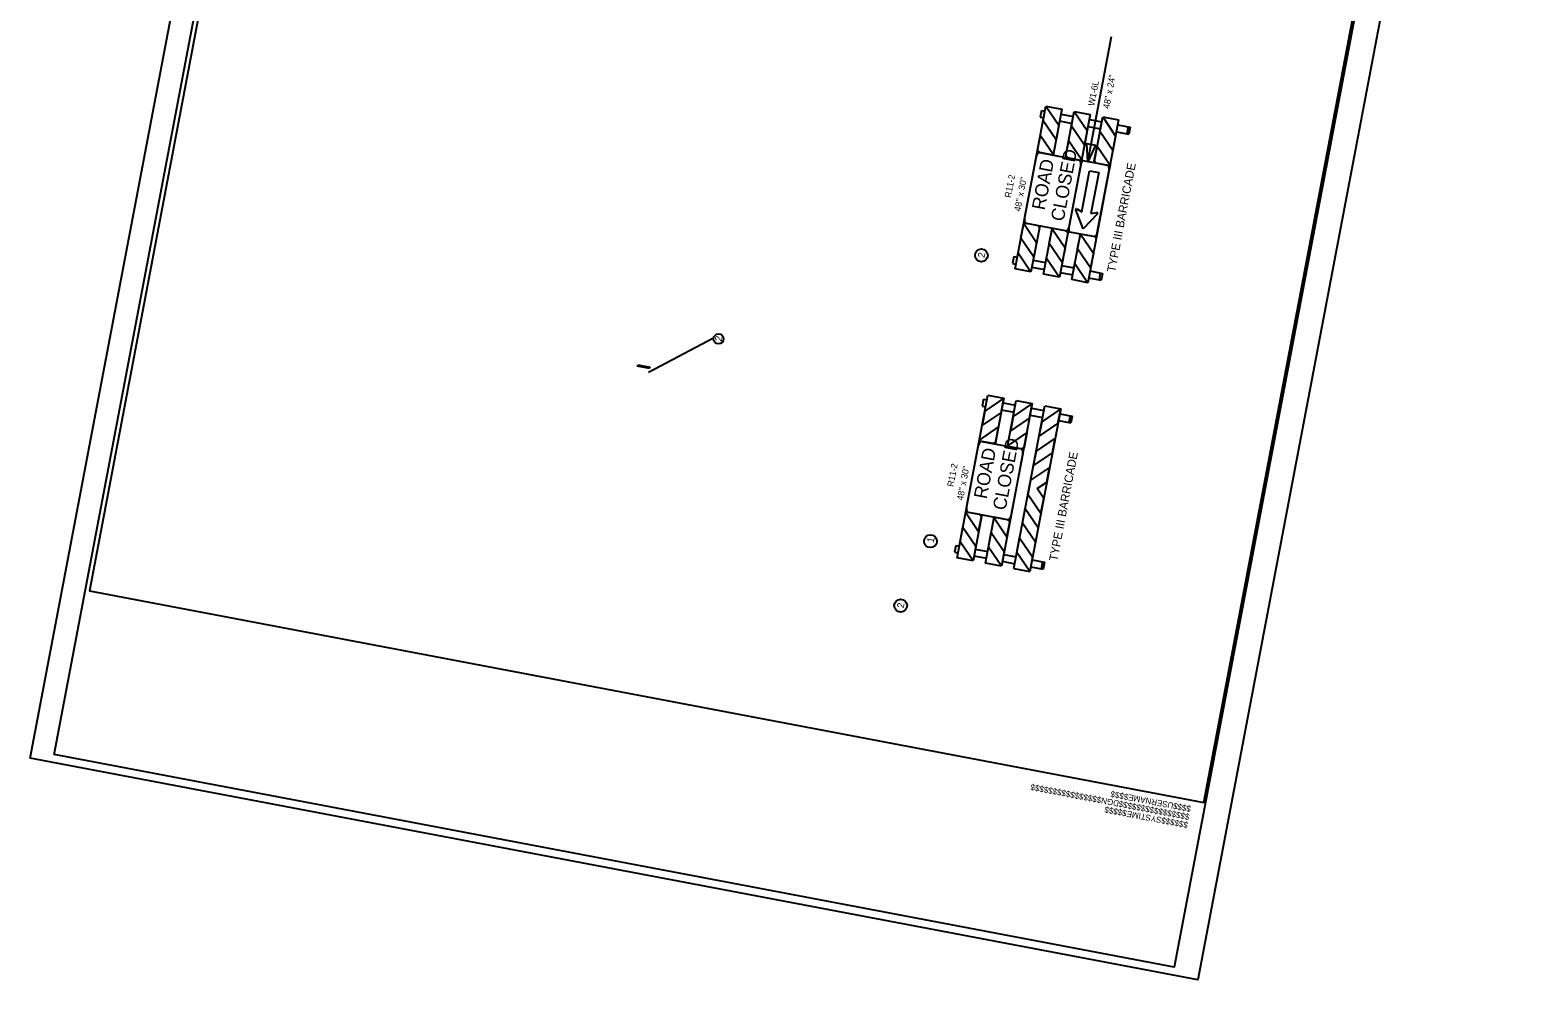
# Model space of a CAD drawing. Extents: x 1615680 to 1619687, y 899305 to 902270.
# Drawn here: x 1618278 to 1619687, y 900389 to 901276 of the extents above; entities that cross this region are included whole.
import ezdxf

# ---------------------------------------------------------------- set-up
doc = ezdxf.new("R2010")
doc.units = 0
for name, color, linetype in [('DEV TYPE 3 BARRICADE CELL', 7, 'Continuous'), ('Prop Mkg Solid Yel Skip RT Rpm 80ft', 7, 'Continuous'), ('Scratch_Level_0', 7, 'Continuous'), ('Scratch_Level_2', 7, 'Continuous'), ('Stage 5', 7, 'Continuous'), ('Stage 6', 7, 'Continuous')]:
    doc.layers.add(name, color=color, linetype=linetype)

msp = doc.modelspace()

# ---------------------------------------------------------------- linework, layer by layer
at = {"layer": 'DEV TYPE 3 BARRICADE CELL'}
for p, q in [((1619144, 900783.3), (1619172.8, 900935.3)), ((1619168.7, 900931.4), (1619167.5, 900925)), ((1619168.7, 900931.4), (1619172, 900930.8)), ((1619187.7, 900932.5), (1619170, 900920.4)), ((1619172.8, 900935.3), (1619187.7, 900932.5)), ((1619187.7, 900932.5), (1619179.6, 900889.6)), ((1619185.1, 900918.8), (1619187.7, 900932.5)), ((1619191.2, 900887.4), (1619199.3, 900930.3)), ((1619199.3, 900930.3), (1619214.2, 900927.5)), ((1619170, 900920.4), (1619167.4, 900906.8)), ((1619167.4, 900906.8), (1619185.1, 900918.8)), ((1619167.5, 900925), (1619170.7, 900924.4)), ((1619214.2, 900927.5), (1619185.4, 900775.5)), ((1619185.6, 900921.5), (1619197.3, 900919.3)), ((1619186.9, 900928), (1619198.5, 900925.8)), ((1619196.5, 900915.4), (1619193.9, 900901.7)), ((1619214.2, 900927.5), (1619196.5, 900915.4)), ((1619197, 900773.3), (1619225.9, 900925.3)), ((1619211.7, 900913.8), (1619214.2, 900927.5)), ((1619240.8, 900922.4), (1619211.9, 900770.4)), ((1619212.2, 900916.5), (1619223.8, 900914.3)), ((1619213.4, 900923), (1619225, 900920.8)), ((1619240.8, 900922.4), (1619223, 900910.4)), ((1619225.9, 900925.3), (1619240.8, 900922.4)), ((1619238.2, 900908.8), (1619240.8, 900922.4)), ((1619239.9, 900917.9), (1619251.5, 900915.7)), ((1619249.6, 900916.1), (1619248.4, 900909.6)), ((1619251.5, 900915.7), (1619250.3, 900909.3)), ((1619164.8, 900893.1), (1619182.5, 900905.2)), ((1619182.5, 900905.2), (1619179.9, 900891.5)), ((1619193.9, 900901.7), (1619211.7, 900913.8)), ((1619223, 900910.4), (1619220.4, 900896.7)), ((1619220.4, 900896.7), (1619238.2, 900908.8)), ((1619238.7, 900911.5), (1619250.3, 900909.3)), ((1619163.9, 900888.6), (1619164.8, 900893.1)), ((1619177.8, 900890), (1619167.1, 900892)), ((1619167.1, 900892), (1619167.1, 900892)), ((1619179.9, 900891.5), (1619177.8, 900890)), ((1619191.2, 900887.4), (1619191.3, 900888)), ((1619203.7, 900885.1), (1619191.2, 900887.4)), ((1619191.3, 900888), (1619209.1, 900900.1)), ((1619206.5, 900886.4), (1619204.2, 900884.9)), ((1619209.1, 900900.1), (1619206.5, 900886.4)), ((1619235.6, 900895.1), (1619217.8, 900883)), ((1619233, 900881.4), (1619235.6, 900895.1)), ((1619205.4, 900880.7), (1619194.3, 900822.2)), ((1619217.8, 900883), (1619215.2, 900869.3)), ((1619215.2, 900869.3), (1619233, 900881.4)), ((1619230.4, 900867.7), (1619212.6, 900855.7)), ((1619227.8, 900854), (1619230.4, 900867.7)), ((1619212.6, 900855.7), (1619210, 900842)), ((1619218.7, 900847.9), (1619227.8, 900854)), ((1619224.9, 900838.8), (1619218.7, 900847.9)), ((1619152.8, 900830.1), (1619152, 900825.6)), ((1619210.2, 900842.9), (1619222.3, 900825.1)), ((1619222.3, 900825.1), (1619224.9, 900838.8)), ((1619152, 900825.6), (1619164.1, 900807.9)), ((1619165.2, 900823.7), (1619154.5, 900825.7)), ((1619154.5, 900825.7), (1619154.5, 900825.7)), ((1619167, 900823.4), (1619158.9, 900780.5)), ((1619164.1, 900807.9), (1619166.7, 900821.5)), ((1619166.7, 900821.5), (1619165.2, 900823.7)), ((1619170.5, 900778.3), (1619178.6, 900821.2)), ((1619178.6, 900821.2), (1619178.5, 900820.6)), ((1619178.5, 900820.6), (1619190.6, 900802.8)), ((1619191.1, 900818.8), (1619178.6, 900821.2)), ((1619190.6, 900802.8), (1619193.2, 900816.5)), ((1619193.2, 900816.5), (1619191.6, 900818.8)), ((1619205, 900815.5), (1619207.6, 900829.2)), ((1619207.6, 900829.2), (1619219.7, 900811.5)), ((1619146.8, 900798.2), (1619149.4, 900811.9)), ((1619149.4, 900811.9), (1619161.5, 900794.2)), ((1619173.3, 900793.2), (1619175.9, 900806.9)), ((1619175.9, 900806.9), (1619188, 900789.1)), ((1619199.8, 900788.2), (1619202.4, 900801.8)), ((1619202.4, 900801.8), (1619214.5, 900784.1)), ((1619217.1, 900797.8), (1619205, 900815.5)), ((1619219.7, 900811.5), (1619217.1, 900797.8)), ((1619142.8, 900794.9), (1619141.6, 900788.5)), ((1619141.6, 900788.5), (1619144.8, 900787.8)), ((1619142.8, 900794.9), (1619146, 900794.3)), ((1619158.9, 900780.5), (1619146.8, 900798.2)), ((1619161.5, 900794.2), (1619158.9, 900780.5)), ((1619160.9, 900791.5), (1619172.6, 900789.3)), ((1619185.4, 900775.5), (1619173.3, 900793.2)), ((1619188, 900789.1), (1619185.4, 900775.5)), ((1619211.9, 900770.4), (1619199.8, 900788.2)), ((1619158.9, 900780.5), (1619144, 900783.3)), ((1619159.7, 900785), (1619171.3, 900782.8)), ((1619185.4, 900775.5), (1619170.5, 900778.3)), ((1619186.2, 900780), (1619197.9, 900777.8)), ((1619187.5, 900786.4), (1619199.1, 900784.2)), ((1619214.5, 900784.1), (1619211.9, 900770.4)), ((1619212.8, 900774.9), (1619224.4, 900772.7)), ((1619214, 900781.4), (1619225.6, 900779.2)), ((1619223.7, 900779.6), (1619222.4, 900773.1)), ((1619225.6, 900779.2), (1619224.4, 900772.7)), ((1619197, 900773.3), (1619211.9, 900770.4))]:
    msp.add_line(p, q, dxfattribs=at)
for points in [[(1619152.8, 900830.1), (1619163.9, 900888.6)], [(1619167.1, 900892), (1619203.7, 900885.1)], [(1619191.1, 900818.8), (1619154.5, 900825.7)]]:
    msp.add_lwpolyline(points, dxfattribs=at)
for centre, major_axis, start_param, end_param in [((1619166.4, 900888.2), (0.73, 3.87), 0, 1.570796), ((1619166.4, 900888.2), (0.73, 3.87), 0, 1.571024), ((1619203, 900881.2), (0.73, 3.87), 4.712389, 6.283185), ((1619203, 900881.2), (0.73, 3.87), 6.074291, 6.283185), ((1619155.2, 900829.6), (-0.73, -3.87), 4.712461, 6.283185), ((1619155.2, 900829.6), (-0.73, -3.87), 4.712162, 6.283185), ((1619191.8, 900822.7), (-0.73, -3.87), 0, 1.571024), ((1619191.8, 900822.7), (-0.73, -3.87), 0, 0.208894)]:
    msp.add_ellipse(centre, major_axis=major_axis, ratio=0.625, start_param=start_param, end_param=end_param, dxfattribs=at)
at = {"layer": 'Prop Mkg Solid Yel Skip RT Rpm 80ft'}
msp.add_line((1618855.6, 900956.7), (1618916.5, 900988.7), dxfattribs=at)
for centre, radius in [((1619166.7, 901065.9), 5.98), ((1618921.1, 900987.8), 4.68), ((1619119.1, 900798.8), 5.98), ((1619091.2, 900738.6), 5.98)]:
    msp.add_circle(centre, radius, dxfattribs=at)
at = {"layer": 'Scratch_Level_0'}
for p, q in [((1619266.1, 901153.4), (1619288.3, 901270.5)), ((1619198.1, 901053.2), (1619227, 901205.3)), ((1619222.9, 901201.3), (1619221.7, 901194.9)), ((1619222.9, 901201.3), (1619226.1, 901200.7)), ((1619224.4, 901191.6), (1619227, 901205.3)), ((1619227, 901205.3), (1619241.9, 901202.4)), ((1619227, 901205.3), (1619239.1, 901187.5)), ((1619241.9, 901202.4), (1619233.8, 901159.6)), ((1619268.4, 901197.4), (1619239.6, 901045.4)), ((1619241, 901197.9), (1619252.7, 901195.7)), ((1619245.4, 901157.3), (1619253.5, 901200.2)), ((1619250.9, 901186.5), (1619253.5, 901200.2)), ((1619253.5, 901200.2), (1619268.4, 901197.4)), ((1619253.5, 901200.2), (1619265.6, 901182.5)), ((1619221.7, 901194.9), (1619224.9, 901194.3)), ((1619236.5, 901173.8), (1619224.4, 901191.6)), ((1619239.1, 901187.5), (1619236.5, 901173.8)), ((1619239.8, 901191.5), (1619251.4, 901189.2)), ((1619263, 901168.8), (1619250.9, 901186.5)), ((1619265.6, 901182.5), (1619263, 901168.8)), ((1619294.9, 901192.4), (1619266.1, 901040.3)), ((1619266.3, 901186.4), (1619278, 901184.2)), ((1619267.6, 901192.9), (1619279.2, 901190.7)), ((1619271.9, 901152.3), (1619280, 901195.2)), ((1619277.4, 901181.5), (1619280, 901195.2)), ((1619280, 901195.2), (1619292.1, 901177.4)), ((1619280, 901195.2), (1619294.9, 901192.4)), ((1619294.1, 901187.8), (1619305.7, 901185.6)), ((1619303.8, 901186), (1619302.5, 901179.5)), ((1619305.7, 901185.6), (1619304.5, 901179.2)), ((1619219.2, 901164.2), (1619221.8, 901177.9)), ((1619221.8, 901177.9), (1619233.9, 901160.2)), ((1619245.7, 901159.2), (1619248.3, 901172.9)), ((1619248.3, 901172.9), (1619260.4, 901155.1)), ((1619289.5, 901163.8), (1619277.4, 901181.5)), ((1619292.1, 901177.4), (1619289.5, 901163.8)), ((1619292.9, 901181.4), (1619304.5, 901179.2)), ((1619220.8, 901161.9), (1619219.2, 901164.2)), ((1619233.8, 901159.6), (1619221.3, 901161.9)), ((1619233.9, 901160.2), (1619233.8, 901159.6)), ((1619247.2, 901157), (1619245.7, 901159.2)), ((1619257.9, 901155), (1619247.2, 901157)), ((1619260.4, 901155.1), (1619259.6, 901150.7)), ((1619272.2, 901154.1), (1619274.8, 901167.8)), ((1619273.7, 901152), (1619272.2, 901154.1)), ((1619274.8, 901167.8), (1619286.9, 901150.1)), ((1619259.5, 901150.6), (1619248.4, 901092.1)), ((1619260.5, 901106.7), (1619267.8, 901145)), ((1619267.8, 901145), (1619276.3, 901143.4)), ((1619276.3, 901143.4), (1619269, 901105)), ((1619284.4, 901149.9), (1619273.7, 901152)), ((1619275, 901087.1), (1619286.1, 901145.6)), ((1619286.9, 901150.1), (1619286.1, 901145.6)), ((1619261.9, 901090.8), (1619254.8, 901108.5)), ((1619255.7, 901109.5), (1619260.5, 901106.7)), ((1619275.1, 901104.6), (1619261.9, 901090.8)), ((1619269, 901105), (1619274.6, 901105.9)), ((1619203.6, 901082.1), (1619206.2, 901095.8)), ((1619206.2, 901095.8), (1619218.3, 901078)), ((1619221.2, 901093.3), (1619213, 901050.4)), ((1619220.9, 901091.7), (1619219.6, 901093.6)), ((1619219.6, 901093.6), (1619221.2, 901093.3)), ((1619221.2, 901093.3), (1619220.9, 901091.7)), ((1619224.6, 901048.2), (1619232.8, 901091.1)), ((1619230.1, 901077), (1619232.7, 901090.7)), ((1619232.7, 901090.7), (1619244.8, 901073)), ((1619247.4, 901086.7), (1619246, 901088.7)), ((1619248.4, 901092.1), (1619247.4, 901086.7)), ((1619251.2, 901043.2), (1619259.3, 901086)), ((1619256.6, 901072), (1619259.2, 901085.7)), ((1619259.2, 901085.7), (1619271.3, 901067.9)), ((1619273.9, 901081.6), (1619272.5, 901083.7)), ((1619275, 901087.1), (1619273.9, 901081.6)), ((1619215.7, 901064.3), (1619203.6, 901082.1)), ((1619218.3, 901078), (1619215.7, 901064.3)), ((1619242.2, 901059.3), (1619230.1, 901077)), ((1619244.8, 901073), (1619242.2, 901059.3)), ((1619268.7, 901054.3), (1619256.6, 901072)), ((1619197, 901064.8), (1619195.8, 901058.4)), ((1619195.8, 901058.4), (1619199, 901057.7)), ((1619197, 901064.8), (1619200.2, 901064.2)), ((1619198.1, 901053.2), (1619201, 901068.4)), ((1619201, 901068.4), (1619213, 901050.4)), ((1619215.1, 901061.4), (1619226.7, 901059.2)), ((1619224.6, 901048.2), (1619227.5, 901063.4)), ((1619227.5, 901063.4), (1619239.6, 901045.4)), ((1619241.6, 901056.3), (1619253.3, 901054.1)), ((1619251.2, 901043.2), (1619254, 901058.3)), ((1619254, 901058.3), (1619266.1, 901040.3)), ((1619271.3, 901067.9), (1619268.7, 901054.3)), ((1619213, 901050.4), (1619198.1, 901053.2)), ((1619213, 901050.4), (1619198.1, 901053.2)), ((1619213.9, 901054.9), (1619225.5, 901052.7)), ((1619239.6, 901045.4), (1619224.6, 901048.2)), ((1619239.6, 901045.4), (1619224.6, 901048.2)), ((1619240.4, 901049.9), (1619252, 901047.7)), ((1619266.1, 901040.3), (1619251.2, 901043.2)), ((1619266.1, 901040.3), (1619251.2, 901043.2)), ((1619266.9, 901044.8), (1619278.5, 901042.6)), ((1619268.2, 901051.3), (1619279.8, 901049.1)), ((1619277.8, 901049.5), (1619276.6, 901043)), ((1619279.8, 901049.1), (1619278.5, 901042.6))]:
    msp.add_line(p, q, dxfattribs=at)
msp.add_lwpolyline([(1619273.2, 901168.8), (1619266.1, 901153.4), (1619265.1, 901170.3)], close=True, dxfattribs=at)
msp.add_lwpolyline([(1619273.2, 901168.8), (1619266.1, 901153.4), (1619265.1, 901170.3)], close=True, dxfattribs=at)
for points in [[(1619207, 901100), (1619218.1, 901158.5)], [(1619221.3, 901161.9), (1619257.9, 901155)], [(1619285.4, 901149.8), (1619261.7, 901154.2)], [(1619259.5, 901150.6), (1619248.4, 901092.1)], [(1619245.3, 901088.7), (1619208.7, 901095.6)], [(1619249.1, 901088), (1619272.8, 901083.5)]]:
    msp.add_lwpolyline(points, dxfattribs=at)
for centre, major_axis, ratio, start_param, end_param in [((1619220.5, 901158.1), (0.73, 3.87), 0.625, 0, 1.570796), ((1619220.5, 901158.1), (0.73, 3.87), 0.625, 6.283185, 6.491582), ((1619257.1, 901151.1), (-0.73, -3.87), 0.625, 1.570796, 3.141593), ((1619257.1, 901151.1), (0.73, 3.87), 0.625, 4.712389, 6.283185), ((1619261, 901150.4), (0.73, 3.87), 0.375009, 0, 1.571024), ((1619283.6, 901146.1), (-0.73, -3.87), 0.625, 1.570796, 3.141593), ((1619284.6, 901145.9), (0.73, 3.87), 0.375009, 4.712389, 6.283185), ((1619209.4, 901099.5), (-0.73, -3.87), 0.625, 4.712162, 6.283185), ((1619255.4, 901108.8), (0.14, 0.735), 0.88, 6.063803, 8.48391), ((1619274.6, 901105.2), (0.14, 0.735), 0.88, 4.082461, 6.502568), ((1619246, 901092.6), (-0.73, -3.87), 0.625, 0, 1.571024), ((1619246, 901092.6), (-0.73, -3.87), 0.625, 0.287132, 1.570688), ((1619249.9, 901091.8), (-0.73, -3.87), 0.375009, 4.712389, 6.283185), ((1619272.5, 901087.5), (-0.73, -3.87), 0.625, 0.287132, 1.570688), ((1619273.5, 901087.3), (0.73, 3.87), 0.375009, 3.141593, 4.712389)]:
    msp.add_ellipse(centre, major_axis=major_axis, ratio=ratio, start_param=start_param, end_param=end_param, dxfattribs=at)
at = {"layer": 'Scratch_Level_2'}
for p, q in [((1618845.3, 900962.4), (1618845.5, 900963.6)), ((1618845.3, 900962.5), (1618845.5, 900963.6)), ((1618846.6, 900963.4), (1618845.3, 900962.4)), ((1618856.6, 900960.3), (1618845.3, 900962.5)), ((1618845.5, 900963.6), (1618846.6, 900963.4)), ((1618845.5, 900963.6), (1618856.8, 900961.4)), ((1618846.3, 900962.2), (1618847.6, 900963.2)), ((1618847.3, 900962.1), (1618846.3, 900962.2)), ((1618848.6, 900963), (1618847.3, 900962.1)), ((1618847.6, 900963.2), (1618848.6, 900963)), ((1618848.3, 900961.9), (1618849.6, 900962.8)), ((1618849.3, 900961.7), (1618848.3, 900961.9)), ((1618850.7, 900962.6), (1618849.3, 900961.7)), ((1618849.6, 900962.8), (1618850.7, 900962.6)), ((1618850.4, 900961.5), (1618851.7, 900962.4)), ((1618851.4, 900961.3), (1618850.4, 900961.5)), ((1618852.7, 900962.2), (1618851.4, 900961.3)), ((1618851.7, 900962.4), (1618852.7, 900962.2)), ((1618852.4, 900961.1), (1618853.7, 900962)), ((1618853.4, 900960.9), (1618852.4, 900961.1)), ((1618854.8, 900961.8), (1618853.4, 900960.9)), ((1618853.7, 900962), (1618854.8, 900961.8)), ((1618854.4, 900960.7), (1618855.8, 900961.6)), ((1618855.4, 900960.5), (1618854.4, 900960.7)), ((1618856.8, 900961.4), (1618855.4, 900960.5)), ((1618855.8, 900961.6), (1618856.8, 900961.4)), ((1618856.8, 900961.4), (1618856.6, 900960.3))]:
    msp.add_line(p, q, dxfattribs=at)
at = {"layer": 'Stage 5'}
msp.add_lwpolyline([(1618277.8, 900596), (1618595.7, 902270.2), (1619686.6, 902063), (1619368.8, 900388.9)], close=True, dxfattribs=at)
at = {"layer": 'Stage 6'}
for points in [[(1618300.1, 900599.5), (1618614, 902252.5), (1619660.8, 902053.7), (1619346.9, 900400.7)], [(1618615.6, 902240), (1618333.2, 900752.3), (1619374.6, 900554.6), (1619657, 902042.3)]]:
    msp.add_lwpolyline(points, close=True, dxfattribs=at)

# ---------------------------------------------------------------- texts
at = {"layer": 'DEV TYPE 3 BARRICADE CELL'}
for s, height, p in [('CLOSED', 12.37, (1619189.3, 900827.1)), ('ROAD', 12.37, (1619171.6, 900837.7)), ('TYPE III BARRICADE', 7.882, (1619237.6, 900779.7)), ('R11-2', 6, (1619140.5, 900849.3)), ("48'' x 30''", 6, (1619149.5, 900836.6))]:
    msp.add_text(s, height=height, rotation=79.2494, dxfattribs=at).set_placement(p)
at = {"layer": 'Prop Mkg Solid Yel Skip RT Rpm 80ft'}
for s, p in [('2', (1619169.5, 901063.2)), ('2', (1618923.9, 900985.1)), ('1', (1619122.1, 900797)), ('2', (1619094, 900735.9))]:
    msp.add_text(s, height=6.5, rotation=79.2494, dxfattribs=at).set_placement(p)
at = {"layer": 'Scratch_Level_0'}
for s, height, p in [('W1-6L', 6, (1619272.1, 901205.2)), ('48" x 24"', 6, (1619286.1, 901202.5)), ('ROAD', 12.37, (1619225.8, 901107.6)), ('CLOSED', 12.37, (1619243.5, 901097.1)), ('R11-2', 6, (1619194.2, 901119.3)), ('TYPE III BARRICADE', 7.882, (1619291.7, 901049.7)), ("48'' x 30''", 6, (1619203.2, 901106.6))]:
    msp.add_text(s, height=height, rotation=79.2494, dxfattribs=at).set_placement(p)
at = {"layer": 'Stage 6'}
for s, p in [('$$$$$$$$$$$$$$$$DGN$$$$$$$$$$$$$$$$', (1619361.6, 900543.7)), ('$$$$USERNAME$$$$', (1619363, 900551.2)), ('$$$$$$SYSTIME$$$$$', (1619360.2, 900536.1))]:
    msp.add_text(s, height=5.637, rotation=169.212, dxfattribs=at).set_placement(p)

doc.saveas('drawing.dxf')
